// Mitsubishi GX Works2 project: 三菱模版   PLC: FX3U/FX3UC

PROGRAM MAIN
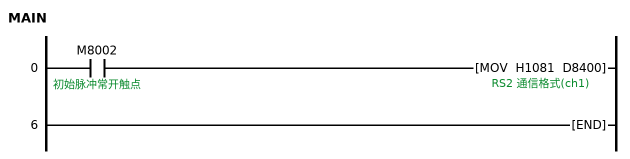
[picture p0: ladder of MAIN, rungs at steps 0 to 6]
0     LD      M8002  ; 初始脉冲常开触点
      MOV     H1081 D8400  ; RS2 通信格式(ch1)
6     END
END_PROGRAM

// device comments not shown above
C10  ; CCD1拍照连续不良计数
C11  ; CCD2连续不良计数
